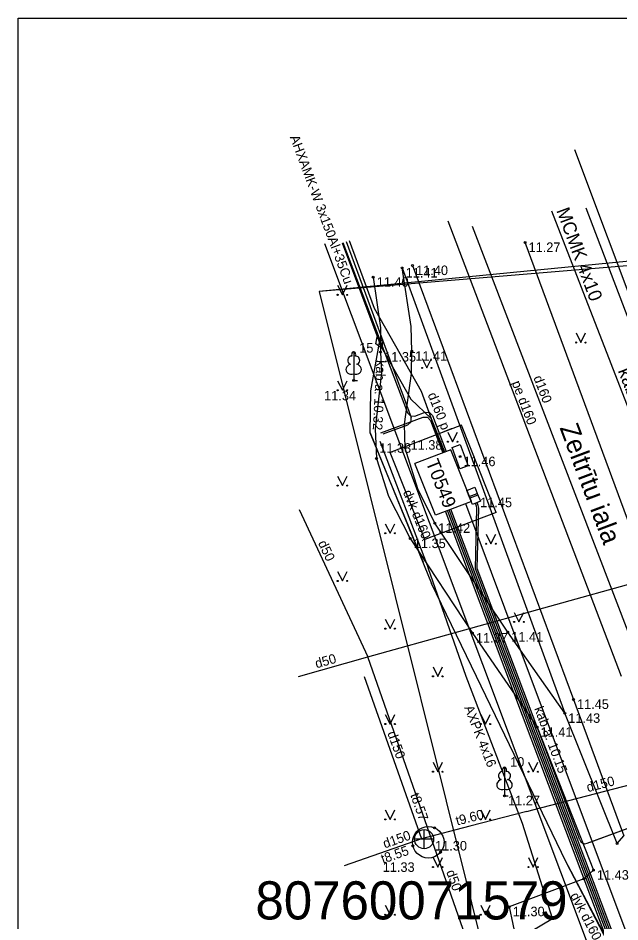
# Model space of a CAD drawing. Extents: x 503353 to 504004, y 304662 to 305049.
# Drawn here: x 503353 to 503384.55, y 304987.12 to 305034.51 of the extents above; entities that cross this region are included whole.
import ezdxf

# ---------------------------------------------------------------- set-up
doc = ezdxf.new("R2010")
doc.units = 0
for name, color, linetype in [('59', 7, 'Continuous'), ('APGR_SARK_####_####_#', 7, 'Continuous'), ('APGS_ACRL_####_####_#', 7, 'Continuous'), ('APGS_ELEM_####_####_#', 7, 'Continuous'), ('APGS_VADP_ZSPR_####_#', 7, 'Continuous'), ('APGS_VADP_ZSPR_TKST_#', 7, 'Continuous'), ('CELI_CMAL_####_####_#', 7, 'Continuous'), ('CELI_IELA_####_TKST_#', 7, 'Continuous'), ('CKOM_ZEMJ_####_####_#', 7, 'Continuous'), ('DREN_VADP_####_####_#', 7, 'Continuous'), ('DREN_VADP_####_TKST_#', 7, 'Continuous'), ('DREN_VADP_KLKT_####_#', 7, 'Continuous'), ('ELEK_ACRL_####_####_#', 7, 'Continuous'), ('ELEK_ACRL_####_TKST_#', 7, 'Continuous'), ('ELEK_ELEM_####_####_#', 7, 'Continuous'), ('ELEK_STTP_####_####_#', 7, 'Continuous'), ('ELEK_STTP_####_TKST_#', 7, 'Continuous'), ('ELEK_VADP_VSPR_####_#', 7, 'Continuous'), ('ELEK_VADP_VSPR_####_I', 7, 'Continuous'), ('ELEK_VADP_VSPR_TKST_#', 7, 'Continuous'), ('ELEK_VADP_ZSPR_####_#', 7, 'Continuous'), ('ELEK_VADP_ZSPR_TKST_#', 7, 'Continuous'), ('GAZE_VADP_VSP2_####_#', 7, 'Continuous'), ('GAZE_VADP_VSP2_TKST_#', 7, 'Continuous'), ('RAMI_PLAN_####_TKST_#', 7, 'Continuous'), ('RAMI_UZMR_####_####_#', 7, 'Continuous'), ('RELJ_AATZ_####_TKST_#', 7, 'Continuous'), ('RELJ_ELEM_####_####_#', 7, 'Continuous'), ('SAKK_KKAN_####_####_#', 7, 'Continuous'), ('SKAN_DETP_PAST_####_#', 7, 'Continuous'), ('SKAN_ELEM_####_####_#', 7, 'Continuous'), ('SKAN_ELEM_PAST_TKST_#', 7, 'Continuous'), ('SKAN_VADP_PAST_####_#', 7, 'Continuous'), ('SKAN_VADP_PAST_TKST_#', 7, 'Continuous'), ('SKAN_VADP_PAST_TKST_I', 7, 'Continuous'), ('TERT_DIAM_####_TKST_#', 7, 'Continuous'), ('TERT_ELEM_####_####_#', 7, 'Continuous'), ('UDTK_VADP_UDEN_####_#', 7, 'Continuous'), ('UDTK_VADP_UDEN_TKST_#', 7, 'Continuous')]:
    doc.layers.add(name, color=color, linetype=linetype)

msp = doc.modelspace()

# ---------------------------------------------------------------- linework, layer by layer
at = {"layer": 'APGR_SARK_####_####_#'}
for p, q in [((503382.16, 305027.621), (503400.006, 304980.111)), ((503369.054, 305022.698), (503383.201, 304985.036))]:
    msp.add_line(p, q, dxfattribs=at)
at = {"layer": 'APGS_ACRL_####_####_#'}
msp.add_line((503382.983, 304991.303), (503391.423, 304994.43), dxfattribs=at)
at = {"layer": 'APGS_ELEM_####_####_#'}
msp.add_lwpolyline([(503377.231, 305009.186), (503376.818, 305009.014), (503376.649, 305009.42), (503377.062, 305009.592)], close=True, dxfattribs=at)
at = {"layer": 'APGS_VADP_ZSPR_####_#'}
for p, q in [((503388.049, 305006.178), (503380.972, 305024.384)), ((503376.973, 305005.637), (503377.051, 305008.81)), ((503377.073, 305005.654), (503377.151, 305008.808)), ((503384.597, 304985.427), (503376.973, 305005.637)), ((503382.443, 304991.421), (503377.073, 305005.654)), ((503382.828, 304991.246), (503392.059, 304994.666))]:
    msp.add_line(p, q, dxfattribs=at)
for points in [[(503377.051, 305008.81), (503377.03, 305008.927), (503376.972, 305009.075)], [(503377.151, 305008.808), (503377.123, 305008.964), (503377.065, 305009.112)]]:
    msp.add_lwpolyline(points, dxfattribs=at)
msp.add_arc((503382.723, 304991.527), 0.3, 200.6691, 290.3306, dxfattribs=at)
at = {"layer": 'CELI_CMAL_####_####_#'}
for points in [[(503393.097, 304986.219), (503379.573, 305022.746)], [(503384.397, 304991.238), (503381.655, 304998.062), (503378.665, 305002.318), (503374.838, 305008.023), (503373.954, 305009.829), (503373.284, 305011.97), (503373.247, 305013.216), (503373.622, 305015.879), (503373.634, 305017.042), (503373.599, 305018.344), (503373.131, 305021.409)], [(503373.131, 305021.409), (503381.655, 304998.062)], [(503373.677, 305021.537), (503382.111, 304998.789), (503384.746, 304991.641)], [(503371.616, 305020.926), (503372.005, 305018.263), (503372.003, 305017.002), (503372.043, 305015.936), (503371.725, 305012.979), (503371.787, 305011.416), (503372.424, 305009.454), (503373.559, 305007.224)], [(503373.559, 305007.224), (503376.813, 305002.269), (503380.203, 304997.331), (503383.156, 304989.838)], [(503384.397, 304991.238), (503384.746, 304991.641)], [(503383.156, 304989.838), (503382.652, 304989.382), (503378.744, 304987.921), (503379.313, 304985.194), (503383.895, 304985.877)]]:
    msp.add_lwpolyline(points, dxfattribs=at)
at = {"layer": 'CKOM_ZEMJ_####_####_#'}
for p, q in [((503376.251, 305013.165), (503372.499, 305011.737)), ((503378.067, 305008.596), (503376.251, 305013.165)), ((503374.315, 305007.168), (503372.499, 305011.737)), ((503378.067, 305008.596), (503374.315, 305007.168))]:
    msp.add_line(p, q, dxfattribs=at)
at = {"layer": 'DREN_VADP_####_####_#'}
for p in [(503367.724, 305008.749), (503367.699, 304999.992), (503378.974, 304979.201)]:
    msp.add_line(p, (503371.327, 305001.016), dxfattribs=at)
at = {"layer": 'DREN_VADP_KLKT_####_#'}
msp.add_line((503371.327, 305001.016), (503395.713, 305007.825), dxfattribs=at)
at = {"layer": 'ELEK_ACRL_####_####_#'}
for p, q in [((503371.663, 305019.296), (503374.122, 305014.958)), ((503371.451, 305012.76), (503374.678, 305004.86)), ((503384.269, 304985.458), (503381.835, 304990.062))]:
    msp.add_line(p, q, dxfattribs=at)
msp.add_lwpolyline([(503374.122, 305014.958), (503375.172, 305012.082)], dxfattribs=at)
at = {"layer": 'ELEK_ELEM_####_####_#'}
for points in [[(503371.826, 305017.799), (503372.126, 305017.571), (503372.052, 305017.2), (503371.752, 305017.429)], [(503376.171, 305012.159), (503376.585, 305011.032), (503376.163, 305010.877), (503375.749, 305012.004)], [(503377.099, 305009.501), (503376.683, 305009.338), (503376.523, 305009.747), (503376.939, 305009.91)]]:
    msp.add_lwpolyline(points, close=True, dxfattribs=at)
at = {"layer": 'ELEK_STTP_####_####_#'}
for p, q in [((503375.686, 305011.88), (503373.803, 305011.163)), ((503376.763, 305009.17), (503375.686, 305011.88)), ((503374.88, 305008.453), (503373.803, 305011.163)), ((503376.763, 305009.17), (503374.88, 305008.453))]:
    msp.add_line(p, q, dxfattribs=at)
at = {"layer": 'ELEK_VADP_VSPR_####_#'}
for p, q in [((503374.73, 305013.67), (503375.447, 305011.789)), ((503372.01, 305012.772), (503374.23, 305013.589)), ((503374.254, 305005.96), (503371.451, 305012.76)), ((503384.489, 304985.431), (503375.688, 305008.76)), ((503377.026, 305000), (503374.678, 305004.86)), ((503381.733, 304990.255), (503377.026, 305000)), ((503385.249, 304983.527), (503381.733, 304990.255))]:
    msp.add_line(p, q, dxfattribs=at)
for points in [[(503369.995, 305022.727), (503372.011, 305017.306), (503373.588, 305014.527), (503374.658, 305013.515), (503375.353, 305011.766)], [(503370.025, 305022.738), (503373.414, 305013.82), (503373.569, 305013.652), (503373.798, 305013.643)], [(503371.451, 305012.76), (503371.486, 305014.968), (503371.939, 305017.5)], [(503373.798, 305013.643), (503374.346, 305013.845), (503374.574, 305013.836), (503374.73, 305013.67)], [(503374.23, 305013.589), (503374.458, 305013.58), (503374.614, 305013.414), (503375.26, 305011.718)]]:
    msp.add_lwpolyline(points, dxfattribs=at)
at = {"layer": 'ELEK_VADP_VSPR_####_I'}
msp.add_lwpolyline([(503370.359, 305022.857), (503371.663, 305019.296), (503374.122, 305014.958), (503375.18, 305012.06), (503375.304, 305011.735)], dxfattribs=at)
at = {"layer": 'ELEK_VADP_ZSPR_####_#'}
for p, q in [((503370.188, 305022.794), (503373.612, 305013.575)), ((503371.962, 305012.325), (503374.489, 305005.69)), ((503384.213, 304985.311), (503375.407, 305008.654)), ((503384.322, 304985.307), (503375.501, 305008.689)), ((503384.529, 304985.04), (503375.594, 305008.725)), ((503376.49, 305000), (503376.485, 305000.013)), ((503381.014, 304987.308), (503379.444, 304992.291))]:
    msp.add_line(p, q, dxfattribs=at)
for points in [[(503372.139, 305012.713), (503373.434, 305013.189), (503373.603, 305013.346), (503373.612, 305013.575)], [(503376.457, 305009.054), (503379.852, 305000)], [(503379.444, 304992.291), (503376.49, 305000), (503374.489, 305005.69)], [(503379.852, 305000), (503395.709, 304957.709)], [(503377.635, 304985.595), (503378.697, 304985.923), (503381.014, 304987.308)]]:
    msp.add_lwpolyline(points, dxfattribs=at)
at = {"layer": 'GAZE_VADP_VSP2_####_#'}
msp.add_lwpolyline([(503384.635, 305000), (503375.541, 305023.856)], dxfattribs=at)
at = {"layer": 'RAMI_PLAN_####_TKST_#'}
msp.add_lwpolyline([(503550.18, 304891.905), (503352.996, 304891.905), (503352.996, 305034.51), (503550.18, 305034.51)], close=True, dxfattribs=at)
at = {"layer": 'RAMI_UZMR_####_####_#'}
for points in [[(503407.219, 305023.925), (503368.776, 305020.183), (503379.431, 304977.462), (503383.452, 304957.421), (503396.867, 304960.598), (503416.959, 304959.032), (503433.698, 304951.36), (503608.791, 304871.751), (503642.724, 304858.177), (503694.651, 304834.724), (503842.283, 304765.867)], [(503825.923, 304784.828), (503697.433, 304847.709), (503608.51, 304889.842), (503606.524, 304897.202), (503679.244, 304999.942), (503684.897, 305009.76), (503666.777, 305017.939), (503656.134, 304996.39), (503644.103, 304987.6), (503600.987, 304924.263), (503587.985, 304916.668), (503422.237, 304989.372), (503408.615, 305023.495), (503368.776, 305020.183)]]:
    msp.add_lwpolyline(points, dxfattribs=at)
at = {"layer": 'RELJ_ELEM_####_####_#'}
for centre in [(503379.573, 305022.746), (503373.131, 305021.409), (503373.677, 305021.537), (503371.616, 305020.926), (503372.003, 305017.002), (503373.634, 305017.042), (503370.59, 305015.517), (503373.284, 305011.97), (503371.787, 305011.416), (503376.167, 305011.518), (503374.838, 305008.023), (503373.559, 305007.224), (503376.813, 305002.269), (503378.665, 305002.318), (503382.111, 304998.789), (503381.655, 304998.062), (503380.203, 304997.331), (503378.496, 304993.741), (503374.83, 304992.057), (503373.696, 304991.116), (503384.397, 304991.238), (503375.14, 304990.778), (503383.156, 304989.838), (503382.652, 304989.382), (503378.744, 304987.921)]:
    msp.add_circle(centre, 0.05, dxfattribs=at)
at = {"layer": 'SAKK_KKAN_####_####_#'}
msp.add_lwpolyline([(503382.758, 305024.558), (503392.141, 305000)], dxfattribs=at)
at = {"layer": 'SKAN_DETP_PAST_####_#'}
msp.add_circle((503374.501, 304991.3), 0.825, dxfattribs=at)
at = {"layer": 'SKAN_ELEM_####_####_#'}
for p, q in [((503374.283, 304990.963), (503374.283, 304991.963)), ((503374.783, 304991.463), (503373.783, 304991.463))]:
    msp.add_line(p, q, dxfattribs=at)
msp.add_circle((503374.283, 304991.463), 0.5, dxfattribs=at)
at = {"layer": 'SKAN_VADP_PAST_####_#'}
for p, q in [((503371.138, 305000), (503374.153, 304991.487)), ((503379.98, 304993.004), (503390.798, 304995.796)), ((503379.66, 304992.921), (503379.98, 304993.004)), ((503374.153, 304991.487), (503370.084, 304990.062))]:
    msp.add_line(p, q, dxfattribs=at)
for points in [[(503379.665, 304992.914), (503376.677, 304992.14)], [(503376.677, 304992.14), (503374.153, 304991.487)]]:
    msp.add_lwpolyline(points, dxfattribs=at)
at = {"layer": 'TERT_ELEM_####_####_#'}
for p, q in [((503369.75, 305020.5), (503370, 305020)), ((503370, 305020), (503370.25, 305020.5)), ((503382.25, 305018), (503382.5, 305017.5)), ((503382.5, 305017.5), (503382.75, 305018)), ((503374.177, 305016.671), (503374.427, 305016.171)), ((503374.427, 305016.171), (503374.677, 305016.671)), ((503370.59, 305015.864), (503370.59, 305015.517)), ((503369.75, 305015.5), (503370, 305015)), ((503370, 305015), (503370.25, 305015.5)), ((503370.59, 305015.517), (503370.79, 305015.517)), ((503375.529, 305012.801), (503375.779, 305012.301)), ((503375.779, 305012.301), (503376.029, 305012.801)), ((503369.75, 305010.5), (503370, 305010)), ((503370, 305010), (503370.25, 305010.5)), ((503372.25, 305008), (503372.5, 305007.5)), ((503372.5, 305007.5), (503372.75, 305008)), ((503377.536, 305007.45), (503377.786, 305006.95)), ((503377.786, 305006.95), (503378.036, 305007.45)), ((503369.75, 305005.5), (503370, 305005)), ((503370, 305005), (503370.25, 305005.5)), ((503379.006, 305003.351), (503379.256, 305002.851)), ((503379.256, 305002.851), (503379.506, 305003.351)), ((503372.25, 305003), (503372.5, 305002.5)), ((503372.5, 305002.5), (503372.75, 305003)), ((503374.75, 305000.5), (503375, 305000)), ((503375, 305000), (503375.25, 305000.5)), ((503372.25, 304998), (503372.5, 304997.5)), ((503372.5, 304997.5), (503372.75, 304998)), ((503377.25, 304998), (503377.5, 304997.5)), ((503377.5, 304997.5), (503377.75, 304998)), ((503374.75, 304995.5), (503375, 304995)), ((503375, 304995), (503375.25, 304995.5)), ((503379.75, 304995.5), (503380, 304995)), ((503380, 304995), (503380.25, 304995.5)), ((503378.496, 304994.088), (503378.496, 304993.741)), ((503378.496, 304993.741), (503378.696, 304993.741)), ((503372.25, 304993), (503372.5, 304992.5)), ((503372.5, 304992.5), (503372.75, 304993)), ((503377.25, 304993), (503377.5, 304992.5)), ((503377.5, 304992.5), (503377.75, 304993)), ((503374.75, 304990.5), (503375, 304990)), ((503375, 304990), (503375.25, 304990.5)), ((503379.75, 304990.5), (503380, 304990)), ((503380, 304990), (503380.25, 304990.5)), ((503372.25, 304988), (503372.5, 304987.5)), ((503372.5, 304987.5), (503372.75, 304988)), ((503377.25, 304988), (503377.5, 304987.5)), ((503377.5, 304987.5), (503377.75, 304988))]:
    msp.add_line(p, q, dxfattribs=at)
for points in [[(503370.59, 305017.017), (503370.59, 305015.864)], [(503370.68, 305016.785), (503370.679, 305016.786)], [(503378.496, 304995.241), (503378.496, 304994.088)], [(503378.586, 304995.009), (503378.585, 304995.01)]]:
    msp.add_lwpolyline(points, dxfattribs=at)
for centre, radius in [((503369.75, 305020), 0.028), ((503370.25, 305020), 0.0263), ((503382.25, 305017.5), 0.028), ((503382.75, 305017.5), 0.0263), ((503374.177, 305016.17), 0.028), ((503374.677, 305016.17), 0.0263), ((503369.75, 305015), 0.028), ((503370.25, 305015), 0.0263), ((503375.529, 305012.301), 0.028), ((503376.029, 305012.301), 0.0263), ((503369.75, 305010), 0.028), ((503370.25, 305010), 0.0263), ((503372.25, 305007.5), 0.028), ((503372.75, 305007.5), 0.0263), ((503377.536, 305006.949), 0.028), ((503378.036, 305006.949), 0.0263), ((503369.75, 305005), 0.028), ((503370.25, 305005), 0.0263), ((503379.006, 305002.85), 0.028), ((503379.506, 305002.85), 0.0263), ((503372.25, 305002.5), 0.028), ((503372.75, 305002.5), 0.0263), ((503374.75, 305000), 0.028), ((503375.25, 305000), 0.0263), ((503372.25, 304997.5), 0.028), ((503372.75, 304997.5), 0.0263), ((503377.25, 304997.5), 0.028), ((503377.75, 304997.5), 0.0263), ((503374.75, 304995), 0.028), ((503375.25, 304995), 0.0263), ((503379.75, 304995), 0.028), ((503380.25, 304995), 0.0263), ((503372.25, 304992.5), 0.028), ((503372.75, 304992.5), 0.0263), ((503377.25, 304992.5), 0.028), ((503377.75, 304992.5), 0.0263), ((503374.75, 304990), 0.028), ((503375.25, 304990), 0.0263), ((503379.75, 304990), 0.028), ((503380.25, 304990), 0.0263), ((503372.25, 304987.5), 0.028), ((503372.75, 304987.5), 0.0263), ((503377.25, 304987.5), 0.028), ((503377.75, 304987.5), 0.0263)]:
    msp.add_circle(centre, radius, dxfattribs=at)
for centre, major_axis, ratio, start_param, end_param in [((503370.59, 305016.867), (0, -0.15), 0.707107, 3.14537, 5.287485), ((503370.59, 305016.867), (0, -0.15), 0.707107, 0.995701, 3.137816), ((503370.462, 305016.572), (-0.039, -0.212), 0.861323, 3.141593, 6.283185), ((503370.718, 305016.572), (0.039, -0.212), 0.861323, 0, 3.141593), ((503370.5, 305016.11), (0.307, 0.095), 0.814445, 1.570796, 4.752015), ((503370.68, 305016.11), (-0.307, 0.095), 0.814445, 1.531171, 4.712389), ((503378.496, 304995.091), (0, -0.15), 0.707107, 3.14537, 5.287485), ((503378.496, 304995.091), (0, -0.15), 0.707107, 0.995701, 3.137816), ((503378.368, 304994.796), (-0.039, -0.212), 0.861323, 3.141593, 6.283185), ((503378.624, 304994.796), (0.039, -0.212), 0.861323, 0, 3.141593), ((503378.406, 304994.334), (0.307, 0.095), 0.814445, 1.570796, 4.752015), ((503378.586, 304994.334), (-0.307, 0.095), 0.814445, 1.531171, 4.712389)]:
    msp.add_ellipse(centre, major_axis=major_axis, ratio=ratio, start_param=start_param, end_param=end_param, dxfattribs=at)
at = {"layer": 'UDTK_VADP_UDEN_####_#'}
msp.add_lwpolyline([(503376.794, 305023.6), (503396.075, 304973.418)], dxfattribs=at)

# ---------------------------------------------------------------- texts
at = {"layer": '59'}
msp.add_text('80760071579', height=2, dxfattribs=at).set_placement((503365.44, 304987.254))
at = {"layer": 'APGS_VADP_ZSPR_TKST_#'}
for s, height, rotation, p in [('MCMK 4x10', 0.6999, 290.3949, (503381.207, 305024.426)), ('kab.a. 10.24', 0.69994, 291.2428, (503384.432, 305016.023))]:
    msp.add_text(s, height=height, rotation=rotation, dxfattribs=at).set_placement(p)
at = {"layer": 'CELI_IELA_####_TKST_#'}
msp.add_text('Zeltrītu iala', height=1, rotation=290.5764, dxfattribs=at).set_placement((503381.377, 305013.035))
at = {"layer": 'DREN_VADP_####_TKST_#'}
for rotation, p in [(294.982, (503368.708, 305006.992)), (15.7609, (503368.645, 305000.415)), (289.317, (503375.433, 304989.755))]:
    msp.add_text('d50', height=0.5, rotation=rotation, dxfattribs=at).set_placement(p)
at = {"layer": 'ELEK_ACRL_####_TKST_#'}
for s, rotation, p in [('d160 pl', 291.5539, (503374.461, 305014.768)), ('dvk d160', 292.346, (503373.163, 305009.655)), ('dvk d160', 297.5912, (503381.925, 304988.511))]:
    msp.add_text(s, height=0.5, rotation=rotation, dxfattribs=at).set_placement(p)
at = {"layer": 'ELEK_STTP_####_TKST_#'}
msp.add_text('T0549', height=0.7, rotation=291.6737, dxfattribs=at).set_placement((503374.359, 305011.222))
at = {"layer": 'ELEK_VADP_VSPR_TKST_#'}
for s, rotation, p in [('AHXAMK-W 3x150Al+35Cu', 290.3765, (503367.239, 305028.27)), ('kab.a. 10.32', 266.9628, (503371.784, 305016.59)), ('kab.a. 10.15', 290.6691, (503380.046, 304998.311))]:
    msp.add_text(s, height=0.5, rotation=rotation, dxfattribs=at).set_placement(p)
at = {"layer": 'ELEK_VADP_ZSPR_TKST_#'}
msp.add_text('AXPK 4x16', height=0.5, rotation=291.4823, dxfattribs=at).set_placement((503376.376, 304998.364))
at = {"layer": 'GAZE_VADP_VSP2_TKST_#'}
msp.add_text('pe d160', height=0.5, rotation=290.868, dxfattribs=at).set_placement((503378.87, 305015.392))
at = {"layer": 'RELJ_AATZ_####_TKST_#'}
for s, p in [(' 11.27', (503379.573, 305022.246)), (' 11.41', (503373.131, 305020.909)), (' 11.40', (503373.677, 305021.037)), (' 11.40', (503371.616, 305020.426)), (' 11.35', (503372.003, 305016.502)), (' 11.41', (503373.634, 305016.542)), (' 11.34', (503368.856, 305014.467)), (' 11.38', (503373.387, 305011.881)), (' 11.33', (503371.746, 305011.721)), (' 11.46', (503376.167, 305011.018)), (' 11.45', (503377.035, 305008.868)), (' 11.42', (503374.838, 305007.523)), (' 11.35', (503373.559, 305006.724)), (' 11.41', (503378.665, 305001.818)), (' 11.37', (503376.813, 305001.769)), (' 11.45', (503382.111, 304998.289)), (' 11.43', (503381.655, 304997.562)), (' 11.41', (503380.203, 304996.831)), (' 11.27', (503378.496, 304993.241)), (' 11.33', (503371.927, 304989.749)), (' 11.43', (503383.156, 304989.338)), (' 11.30', (503378.744, 304987.421))]:
    msp.add_text(s, height=0.5, dxfattribs=at).set_placement(p)
at = {"layer": 'SKAN_ELEM_PAST_TKST_#'}
msp.add_text('11.30', height=0.5, dxfattribs=at).set_placement((503374.857, 304990.869))
at = {"layer": 'SKAN_VADP_PAST_TKST_#'}
for s, rotation, p in [('d150', 289.5023, (503372.35, 304997.027)), ('d150', 14.3983, (503382.871, 304993.928)), ('t8.57', 289.5028, (503373.552, 304993.781)), ('t9.60', 14.5139, (503376.014, 304992.173)), ('d150', 19.3007, (503372.227, 304990.972))]:
    msp.add_text(s, height=0.5, rotation=rotation, dxfattribs=at).set_placement(p)
at = {"layer": 'SKAN_VADP_PAST_TKST_I'}
msp.add_text('t8.55', height=0.5, rotation=19.3007, dxfattribs=at).set_placement((503372.128, 304990.173))
at = {"layer": 'TERT_DIAM_####_TKST_#'}
for s, p in [('15', (503370.881, 305016.97)), ('10', (503378.792, 304995.263))]:
    msp.add_text(s, height=0.5, dxfattribs=at).set_placement(p)
at = {"layer": 'UDTK_VADP_UDEN_TKST_#'}
msp.add_text('d160', height=0.5, rotation=291.084, dxfattribs=at).set_placement((503380.003, 305015.661))

doc.saveas('drawing.dxf')
